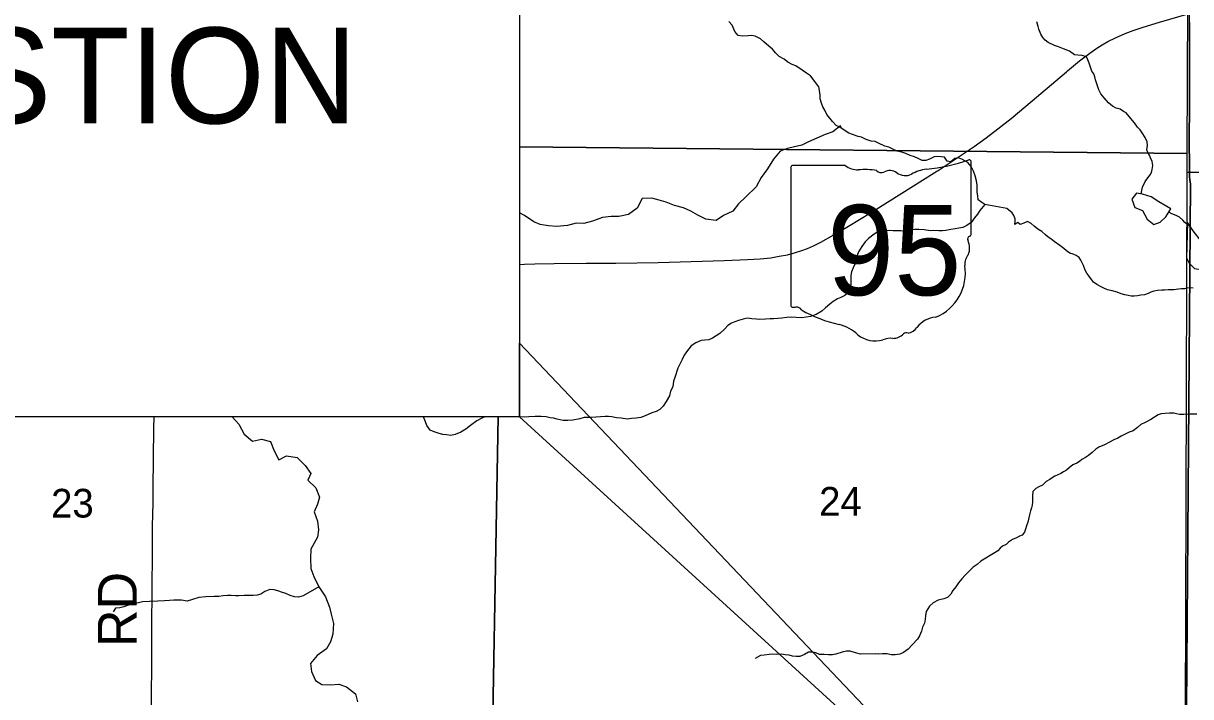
# Model space of a CAD drawing. Extents: x 0 to 34, y 0 to 22.
# Drawn here: x 3.95 to 5.655, y 18.105 to 19.089 of the extents above; entities that cross this region are included whole.
import ezdxf

# ---------------------------------------------------------------- set-up
doc = ezdxf.new("R2010")
doc.units = 0
for name, color, linetype in [('Default', 7, 'Continuous'), ('GM_X_County_Road', 7, 'Continuous'), ('GM_X_County_Road_Text', 7, 'Continuous'), ('GM_X_Minor_Lake', 7, 'Continuous'), ('GM_X_Minor_River', 7, 'Continuous'), ('GM_X_Section', 7, 'Continuous'), ('GM_X_Section_Text', 7, 'Continuous'), ('GM_X_State_Location', 7, 'Continuous'), ('GM_X_State_Route', 7, 'Continuous'), ('GM_X_State_Shield', 7, 'Continuous'), ('GM_X_Township_Road', 7, 'Continuous'), ('SH_Text', 7, 'Continuous')]:
    doc.layers.add(name, color=color, linetype=linetype)

msp = doc.modelspace()

# ---------------------------------------------------------------- linework, layer by layer
at = {"layer": 'Default'}
msp.add_lwpolyline([(4.6746, 18.6215), (5.442, 17.8135), (4.6746, 18.514)], close=True, dxfattribs=at)
at = {"layer": 'GM_X_County_Road'}
msp.add_lwpolyline([(4.1354, 17.891), (4.1352, 17.8945), (4.1354, 17.9162), (4.1358, 17.9597), (4.1364, 18.0001), (4.1364, 18.0187), (4.1366, 18.0684), (4.1368, 18.1057), (4.1371, 18.1523), (4.1375, 18.2238), (4.1376, 18.2455), (4.1378, 18.2735), (4.1381, 18.3045), (4.1385, 18.3542), (4.139, 18.3884), (4.139, 18.4101), (4.1404, 18.4971), (4.1405, 18.514)], dxfattribs=at)
at = {"layer": 'GM_X_Minor_Lake'}
for points in [[(5.6258, 18.8178), (5.6087, 18.8279), (5.5973, 18.8354), (5.5844, 18.8395), (5.5757, 18.8409), (5.5689, 18.8318), (5.5732, 18.82), (5.5846, 18.8152), (5.5915, 18.8027), (5.601, 18.7948), (5.6104, 18.7983), (5.6187, 18.806)], [(5.6187, 18.806), (5.6258, 18.8178)], [(5.649, 18.7459), (5.6533, 18.738), (5.6605, 18.7308), (5.6726, 18.729), (5.6878, 18.7329), (5.6994, 18.7413), (5.6975, 18.7546), (5.6864, 18.7595), (5.6708, 18.77), (5.6586, 18.7858), (5.6502, 18.7979)], [(5.6502, 18.7979), (5.649, 18.7459)]]:
    msp.add_lwpolyline(points, dxfattribs=at)
at = {"layer": 'GM_X_Minor_River'}
for points in [[(5.3542, 18.8243), (5.35, 18.8273), (5.3447, 18.8311), (5.3439, 18.8368), (5.3431, 18.8421), (5.3431, 18.8524), (5.3419, 18.8589), (5.3403, 18.8661), (5.3376, 18.8729), (5.3342, 18.8797), (5.3292, 18.8854), (5.3209, 18.8903), (5.3155, 18.8922), (5.3102, 18.8914), (5.3046, 18.8864), (5.2992, 18.8876), (5.2954, 18.8932), (5.2905, 18.894), (5.2855, 18.8943), (5.2802, 18.8936), (5.2734, 18.8905), (5.2681, 18.8886), (5.2628, 18.8885), (5.2567, 18.8912), (5.2514, 18.8938), (5.2453, 18.8957), (5.2388, 18.8987), (5.2328, 18.9006), (5.2263, 18.9021), (5.2206, 18.9043), (5.2141, 18.9081), (5.208, 18.9096), (5.1989, 18.9137), (5.194, 18.916), (5.1883, 18.9167), (5.1807, 18.9193), (5.1742, 18.9224), (5.1693, 18.9235), (5.1609, 18.9265), (5.1556, 18.9284), (5.1502, 18.9317), (5.1422, 18.937), (5.1369, 18.9397), (5.1319, 18.9454), (5.1277, 18.9503), (5.1235, 18.9556), (5.1205, 18.962), (5.1178, 18.967), (5.1155, 18.9723), (5.1139, 18.9787), (5.1135, 18.9841), (5.1127, 18.9905), (5.1116, 18.9962), (5.1058, 19.0038), (5.0997, 19.0121), (5.0936, 19.0159), (5.0872, 19.0204), (5.078, 19.0269), (5.0727, 19.0287), (5.0666, 19.0321), (5.0613, 19.0363), (5.0537, 19.0404), (5.0483, 19.0457), (5.0441, 19.051), (5.0388, 19.0556), (5.0315, 19.0616), (5.0266, 19.0662), (5.0186, 19.0699), (5.0136, 19.071), (5.0083, 19.0706), (5.0004, 19.0702), (4.9939, 19.071), (4.9889, 19.077), (4.9851, 19.0861), (4.9805, 19.0914)], [(5.5829, 18.8397), (5.5846, 18.8497), (5.5883, 18.8577), (5.5924, 18.8631), (5.5957, 18.8673), (5.5976, 18.8711), (5.5987, 18.8753), (5.5997, 18.8814), (5.5989, 18.8871), (5.5962, 18.8924), (5.5946, 18.8962), (5.5923, 18.9003), (5.5911, 18.9041), (5.5921, 18.9106), (5.5913, 18.9155), (5.5886, 18.9223), (5.5839, 18.9291), (5.5812, 18.9332), (5.5773, 18.9373), (5.5731, 18.9437), (5.565, 18.9528), (5.5607, 18.958), (5.5569, 18.9602), (5.5519, 18.9636), (5.5462, 18.965), (5.5408, 18.9676), (5.5347, 18.9725), (5.5285, 18.98), (5.5235, 18.9856), (5.5207, 18.9917), (5.5172, 19.0019), (5.516, 19.0064), (5.5148, 19.0106), (5.5136, 19.0151), (5.5105, 19.0189), (5.5085, 19.0246), (5.5069, 19.0306), (5.5046, 19.0355), (5.5026, 19.04), (5.4965, 19.0419), (5.49, 19.0422), (5.4854, 19.0429), (5.4778, 19.0481), (5.4694, 19.0514), (5.4617, 19.0547), (5.456, 19.0565), (5.4468, 19.061), (5.4422, 19.0643), (5.4391, 19.0681), (5.436, 19.073), (5.4332, 19.0801), (5.432, 19.0843), (5.4304, 19.0911)], [(5.1447, 18.9354), (5.1436, 18.9393), (5.1323, 18.9305), (5.1209, 18.9262), (5.0968, 18.9155), (5.0869, 18.9109), (5.0763, 18.9085), (5.0658, 18.9058), (5.0555, 18.9023), (5.0454, 18.8905), (5.0368, 18.8761), (5.0277, 18.8635), (5.0202, 18.8498), (5.0052, 18.8353), (4.9946, 18.8254), (4.9863, 18.8143), (4.9724, 18.8082), (4.9618, 18.8009), (4.9466, 18.8027), (4.9352, 18.8087), (4.9246, 18.8147), (4.914, 18.8192), (4.9011, 18.8229), (4.8886, 18.8278), (4.8787, 18.8304), (4.8677, 18.8334), (4.8537, 18.8329), (4.8462, 18.8188), (4.8337, 18.8096), (4.8194, 18.8065), (4.8084, 18.8065), (4.7959, 18.8052), (4.7812, 18.7999), (4.7683, 18.7964), (4.7573, 18.7967), (4.7448, 18.7936), (4.7289, 18.792), (4.7168, 18.793), (4.7047, 18.7952), (4.6952, 18.799), (4.6815, 18.808), (4.6746, 18.8118)], [(5.3542, 18.8243), (5.3471, 18.8152), (5.3437, 18.8102), (5.3391, 18.8045), (5.3342, 18.798), (5.3282, 18.7934), (5.3221, 18.7907), (5.3164, 18.7895), (5.3111, 18.7888), (5.3047, 18.7876), (5.2975, 18.7864), (5.2922, 18.7856), (5.2872, 18.7856), (5.28, 18.786), (5.2747, 18.7859), (5.2656, 18.787), (5.2576, 18.7878), (5.2519, 18.7877), (5.2463, 18.7866), (5.2413, 18.7858), (5.2364, 18.7854), (5.2315, 18.7857), (5.2205, 18.7857), (5.2151, 18.786), (5.2098, 18.7856), (5.2041, 18.7852), (5.1981, 18.7841), (5.1928, 18.781), (5.1845, 18.7745), (5.1795, 18.7699), (5.1747, 18.7627), (5.1698, 18.755), (5.1679, 18.7497), (5.1668, 18.744), (5.1653, 18.739), (5.1619, 18.7318), (5.1597, 18.7257), (5.1586, 18.7204), (5.1586, 18.7097), (5.1579, 18.7029), (5.1564, 18.6972), (5.1496, 18.6914), (5.1439, 18.6884), (5.139, 18.6865), (5.1329, 18.6826), (5.128, 18.6788), (5.1216, 18.6731), (5.1163, 18.6685), (5.108, 18.6635), (5.0997, 18.6608), (5.0932, 18.6596), (5.0868, 18.6588), (5.0788, 18.6592), (5.0716, 18.6595), (5.0648, 18.6591), (5.0576, 18.6583), (5.0519, 18.6575), (5.0454, 18.6571), (5.0405, 18.6571), (5.034, 18.6567), (5.0257, 18.6563), (5.0207, 18.6566), (5.0139, 18.657), (5.0071, 18.6581), (5.001, 18.6566), (4.9942, 18.655), (4.9889, 18.6527), (4.984, 18.6508), (4.979, 18.6477), (4.9741, 18.642), (4.9673, 18.6359), (4.9564, 18.629), (4.9511, 18.6263), (4.945, 18.6259), (4.9397, 18.6255), (4.9321, 18.6224), (4.9253, 18.6178), (4.9185, 18.609), (4.9151, 18.6041), (4.9121, 18.5976), (4.908, 18.59), (4.9058, 18.585), (4.9013, 18.5713), (4.8994, 18.5664), (4.8983, 18.558), (4.8949, 18.5515), (4.8934, 18.5447), (4.8886, 18.5367), (4.8844, 18.5298), (4.8795, 18.5248), (4.8742, 18.5221), (4.8678, 18.5198), (4.8579, 18.5156), (4.8519, 18.5133), (4.845, 18.5121), (4.8382, 18.5117), (4.8321, 18.5109), (4.823, 18.512), (4.8162, 18.5124), (4.8094, 18.5139), (4.8044, 18.5146)], [(5.3968, 18.8081), (5.3941, 18.8118), (5.3864, 18.8186), (5.3542, 18.8243)], [(5.6501, 18.795), (5.6465, 18.7977), (5.6434, 18.8015), (5.6388, 18.8056), (5.6338, 18.8082), (5.6273, 18.8108), (5.623, 18.813)], [(5.6587, 18.7018), (5.6545, 18.7025), (5.6496, 18.702), (5.6458, 18.7012), (5.6416, 18.7008), (5.6371, 18.7003), (5.6302, 18.6995), (5.6264, 18.6998), (5.6219, 18.6998), (5.6166, 18.6993), (5.6128, 18.6993), (5.6063, 18.6984), (5.6014, 18.6976), (5.5968, 18.696), (5.593, 18.6944), (5.5877, 18.6921), (5.5824, 18.6916), (5.5775, 18.6908), (5.5726, 18.6904), (5.568, 18.6903), (5.5638, 18.6914), (5.5588, 18.6925), (5.5535, 18.6939), (5.5474, 18.6961), (5.5401, 18.6979), (5.5336, 18.6997), (5.5279, 18.7019), (5.5241, 18.7038), (5.5179, 18.7075), (5.513, 18.7108), (5.5103, 18.7146), (5.506, 18.7202), (5.5033, 18.724), (5.5009, 18.7282), (5.4982, 18.735), (5.4966, 18.7391), (5.4947, 18.7429), (5.492, 18.7467), (5.4877, 18.7496), (5.4835, 18.7515), (5.4786, 18.7533), (5.4736, 18.7567), (5.4697, 18.7597), (5.464, 18.7645), (5.4555, 18.7701), (5.4505, 18.7742), (5.4467, 18.7764), (5.4428, 18.7798), (5.4375, 18.7847), (5.4317, 18.7884), (5.4263, 18.7925), (5.4221, 18.7966), (5.4167, 18.7996), (5.4114, 18.7969), (5.4061, 18.7949), (5.4023, 18.7979), (5.3982, 18.7948), (5.3985, 18.7993), (5.3984, 18.8031), (5.3968, 18.8081)], [(4.2548, 18.514), (4.2643, 18.5033), (4.2723, 18.4889), (4.2845, 18.4787), (4.2974, 18.4814), (4.3106, 18.4781), (4.316, 18.4645), (4.3229, 18.4513), (4.3342, 18.457), (4.3494, 18.4548), (4.3612, 18.4428), (4.3696, 18.4314), (4.3651, 18.4215), (4.3769, 18.4102), (4.3823, 18.3966), (4.3793, 18.3867), (4.3744, 18.3753), (4.3791, 18.3617), (4.3807, 18.3492), (4.3792, 18.3382), (4.3694, 18.321), (4.3691, 18.3074), (4.3696, 18.2926), (4.3738, 18.2809), (4.3815, 18.2657), (4.391, 18.251), (4.3968, 18.2362), (4.3995, 18.226), (4.4026, 18.212), (4.4016, 18.1968)], [(4.624, 18.514), (4.6192, 18.5122), (4.612, 18.508), (4.603, 18.5015), (4.5962, 18.4962), (4.5886, 18.4916), (4.5806, 18.4885), (4.5742, 18.4869), (4.5677, 18.4877), (4.5624, 18.4884), (4.5571, 18.4899), (4.5499, 18.4921), (4.5438, 18.4944), (4.5392, 18.5016), (4.5373, 18.5069), (4.5342, 18.514)], [(4.8044, 18.5146), (4.7995, 18.5146), (4.793, 18.5142), (4.7858, 18.5137), (4.7794, 18.5133), (4.7744, 18.5129), (4.7688, 18.5129), (4.7627, 18.5114), (4.7525, 18.509), (4.7452, 18.5086), (4.738, 18.5086), (4.7297, 18.5108), (4.724, 18.5123), (4.719, 18.5127), (4.7133, 18.5142), (4.7061, 18.5145), (4.6974, 18.5145), (4.6879, 18.5141), (4.6811, 18.5136), (4.6746, 18.514)], [(5.6638, 18.518), (5.6543, 18.5179), (5.6452, 18.5174), (5.6387, 18.5177), (5.6345, 18.5187), (5.6303, 18.5194), (5.6242, 18.5194), (5.6178, 18.5189), (5.6121, 18.5184), (5.6075, 18.5172), (5.6019, 18.5137), (5.597, 18.5103), (5.5886, 18.506), (5.5822, 18.5028), (5.5773, 18.4986), (5.5709, 18.4936), (5.5653, 18.4916), (5.5581, 18.4885), (5.5532, 18.4857), (5.5486, 18.483), (5.5426, 18.4807), (5.5362, 18.4772), (5.529, 18.4733), (5.521, 18.4697), (5.5165, 18.467), (5.5109, 18.462), (5.5056, 18.4574), (5.5015, 18.4547), (5.4962, 18.4516), (5.4924, 18.4488), (5.4886, 18.4465), (5.483, 18.4438), (5.4777, 18.4395), (5.4736, 18.4361), (5.4694, 18.4337), (5.4653, 18.4314), (5.4611, 18.4294), (5.4566, 18.4275), (5.4528, 18.4248), (5.449, 18.4224), (5.4441, 18.4197), (5.4385, 18.4143), (5.4332, 18.4116), (5.429, 18.4093), (5.4245, 18.405), (5.4238, 18.3985), (5.424, 18.3898), (5.4233, 18.3852), (5.4225, 18.3814), (5.4211, 18.3769), (5.4196, 18.3711), (5.4182, 18.3647), (5.4171, 18.3601), (5.4149, 18.3547), (5.4138, 18.3498), (5.412, 18.3456), (5.409, 18.3414), (5.4048, 18.3398), (5.4007, 18.3375), (5.3946, 18.3351), (5.389, 18.3312), (5.3852, 18.3278), (5.3803, 18.3254), (5.3765, 18.3223), (5.3732, 18.3185), (5.3694, 18.3158)], [(5.3694, 18.3158), (5.3482, 18.3034), (5.3429, 18.2984), (5.3373, 18.2946), (5.3256, 18.2828), (5.3206, 18.2774), (5.3157, 18.2717), (5.312, 18.266), (5.3075, 18.2606), (5.3048, 18.2553), (5.2995, 18.2503), (5.2942, 18.2484), (5.2863, 18.2465), (5.2787, 18.2426), (5.2734, 18.2377), (5.2685, 18.2297), (5.2678, 18.2236), (5.2671, 18.2186), (5.2663, 18.2125), (5.2633, 18.2068), (5.2618, 18.2011), (5.2588, 18.1943), (5.2558, 18.1893), (5.2483, 18.1809), (5.2422, 18.1748), (5.2354, 18.1698), (5.2301, 18.1675), (5.2233, 18.1663), (5.2176, 18.1667), (5.2115, 18.1678), (5.2047, 18.1678), (5.1994, 18.1674), (5.1945, 18.1677), (5.1725, 18.1676), (5.1652, 18.1695), (5.1576, 18.1717), (5.1523, 18.1717), (5.1459, 18.1705), (5.1368, 18.1675), (5.1315, 18.1667), (5.1258, 18.1666), (5.1193, 18.167), (5.1125, 18.167), (5.1076, 18.1692), (5.1026, 18.1703), (5.0965, 18.1703), (5.0909, 18.1669), (5.0841, 18.1638), (5.0787, 18.1638), (5.0734, 18.1645), (5.0685, 18.166), (5.0628, 18.1667), (5.0578, 18.1675), (5.0506, 18.1671), (5.0446, 18.1674), (5.0393, 18.167), (5.0317, 18.1662), (5.0264, 18.1654), (5.0188, 18.1612)], [(4.3815, 18.2657), (4.3584, 18.2525), (4.3515, 18.2506), (4.3455, 18.2513), (4.3394, 18.2532), (4.3329, 18.2562), (4.328, 18.2573), (4.3215, 18.2599), (4.3162, 18.2614), (4.3097, 18.2621), (4.3025, 18.2591), (4.2965, 18.2552), (4.2912, 18.2537), (4.2855, 18.2533), (4.2722, 18.2529), (4.2646, 18.2528), (4.2597, 18.2528), (4.2532, 18.2531), (4.2479, 18.2531), (4.2415, 18.2527), (4.235, 18.2519), (4.2286, 18.2515), (4.2164, 18.2511), (4.2058, 18.2503), (4.1967, 18.2472), (4.1891, 18.2449), (4.1804, 18.2463), (4.1694, 18.2463), (4.1633, 18.2459), (4.1557, 18.2455), (4.1463, 18.2447), (4.1341, 18.2446), (4.1239, 18.2438), (4.1178, 18.2426), (4.1129, 18.2415), (4.1072, 18.2403), (4.1019, 18.2384), (4.0962, 18.2365), (4.0905, 18.2349), (4.0844, 18.2345), (4.0807, 18.2292)], [(4.4016, 18.1968), (4.3982, 18.1854), (4.3926, 18.1752), (4.3786, 18.1656), (4.3692, 18.1538), (4.3708, 18.142), (4.3762, 18.1288), (4.3857, 18.1231), (4.3982, 18.1225), (4.4103, 18.1237), (4.4217, 18.1199), (4.4346, 18.1094), (4.4377, 18.0977)]]:
    msp.add_lwpolyline(points, dxfattribs=at)
at = {"layer": 'GM_X_Section'}
for points in [[(4.6746, 18.9086), (5.6498, 18.8985), (5.6542, 19.8813), (5.654, 19.9264), (4.6576, 19.9182), (4.6526, 19.2311), (4.6746, 19.2311)], [(5.6542, 19.8813), (6.7799, 19.8913), (6.7847, 18.8752), (5.6499, 18.8708), (5.6498, 18.8985)], [(4.6433, 18.514), (4.6321, 17.8882), (5.6468, 17.9172), (5.6499, 18.8708), (5.6498, 18.8985), (4.6746, 18.9086), (4.6746, 18.514)], [(5.6499, 18.8708), (6.7847, 18.8752), (6.7979, 17.8558), (5.6465, 17.841), (5.6468, 17.9172)], [(3.6261, 18.514), (3.6191, 17.892), (4.6321, 17.8882), (4.6433, 18.514)]]:
    msp.add_lwpolyline(points, close=True, dxfattribs=at)
at = {"layer": 'GM_X_State_Route'}
for points in [[(5.4752, 19.0193), (5.4928, 19.0339), (5.5076, 19.0453), (5.5177, 19.0525), (5.5256, 19.0575), (5.5338, 19.0621), (5.545, 19.0676), (5.5593, 19.0738), (5.5709, 19.0782), (5.5857, 19.0832), (5.6095, 19.0904), (5.6512, 19.1027), (5.6535, 19.1034)], [(5.6532, 19.0901), (5.6531, 19.0435), (5.6533, 19.0031), (5.6534, 18.969), (5.653, 18.9193), (5.6529, 18.9045), (5.6531, 18.8925), (5.6534, 18.8695), (5.6535, 18.8651), (5.654, 18.8601), (5.6549, 18.8539), (5.6477, 17.9606)], [(5.6477, 17.9606), (5.6549, 18.8539), (5.654, 18.8601), (5.6535, 18.8651), (5.6534, 18.8695), (5.6531, 18.8925), (5.6529, 18.9045), (5.653, 18.9193), (5.6534, 18.969), (5.6533, 19.0031), (5.6531, 19.0435), (5.6532, 19.0901)], [(5.286, 18.8738), (5.3051, 18.8863), (5.3386, 18.9088), (5.3562, 18.9215), (5.3735, 18.9346), (5.3929, 18.95), (5.4144, 18.9679), (5.4737, 19.018), (5.4752, 19.0193)], [(4.6746, 18.7366), (4.6815, 18.7369), (4.697, 18.7373), (4.725, 18.738), (4.7716, 18.7384), (4.8151, 18.7386), (4.8772, 18.7395), (4.9734, 18.7423), (5.0076, 18.7437), (5.0261, 18.7449), (5.0415, 18.7465), (5.0537, 18.7485), (5.0659, 18.7509), (5.0778, 18.754), (5.0867, 18.7568), (5.0953, 18.7601), (5.1038, 18.7638), (5.1148, 18.7694), (5.1337, 18.7801), (5.1552, 18.7926), (5.1871, 18.8118), (5.2161, 18.8298), (5.2634, 18.8595), (5.2843, 18.8728), (5.286, 18.8738)]]:
    msp.add_lwpolyline(points, dxfattribs=at)
at = {"layer": 'GM_X_State_Shield'}
for p, q in [((5.1504, 18.8811), (5.0732, 18.8811)), ((5.3343, 18.7814), (5.3343, 18.8861)), ((5.0706, 18.8777), (5.0706, 18.6776)), ((5.3343, 18.7814), (5.3343, 18.7814))]:
    msp.add_line(p, q, dxfattribs=at)
for centre, radius, start, end in [((5.0736, 18.8781), 0.00305, 98.1301, 188.1301), ((5.1688, 18.9044), 0.0296, 231.6195, 271.1119), ((5.2404, 19.154), 0.2796, 275.8445, 288.9065), ((5.3314, 18.8865), 0.00294, 351.8621, 97.738), ((5.1787, 18.7688), 0.1064, 80.4867, 94.9883), ((5.2028, 18.8792), 0.00855, 219.7921, 297.1024), ((5.2153, 18.856), 0.0178, 54.4667, 119.1411), ((5.2383, 18.8878), 0.0214, 233.8562, 294.8282), ((5.276, 18.82), 0.0563, 97.3462, 120.7689), ((5.3336, 18.7737), 0.00454, 107.944, 210.337), ((5.3312, 18.781), 0.00314, 289.6038, 7.7341), ((5.3047, 18.7605), 0.0273, 340.033, 23.6496), ((5.3448, 18.7376), 0.0198, 136.8065, 186.9296), ((5.256, 18.7243), 0.0699, 292.3089, 8.9858), ((5.0737, 18.6771), 0.00308, 171.9584, 258.3066), ((5.0741, 18.6976), 0.0235, 267.339, 280.6039), ((5.079, 18.666), 0.00848, 29.7484, 93.2717), ((5.186, 18.8458), 0.2019, 240.4129, 257.1985), ((5.2855, 18.6214), 0.0383, 94.4031, 142.5768), ((5.1258, 18.5877), 0.0632, 47.1842, 75.836), ((5.237, 18.6582), 0.0226, 282.8732, 323.2771), ((5.1941, 18.665), 0.0401, 230.7004, 286.2918), ((5.2173, 18.5959), 0.0329, 85.6951, 111.2099), ((5.2202, 18.6501), 0.0214, 268.777, 315.5493), ((5.2396, 18.6307), 0.00601, 65.7517, 132.6484)]:
    msp.add_arc(centre, radius, start, end, dxfattribs=at)
at = {"layer": 'GM_X_Township_Road'}
msp.add_lwpolyline([(5.6551, 18.8533), (5.6542, 18.8596), (5.6537, 18.8646), (5.6536, 18.869), (5.6533, 18.8919), (5.6531, 18.904), (5.6532, 18.9188), (5.6536, 18.9685), (5.6535, 19.0026), (5.6533, 19.0429), (5.6534, 19.0895), (5.6535, 19.1034)], dxfattribs=at)
at = {"layer": 'SH_Text'}
msp.add_lwpolyline([(2.4548, 19.2311), (4.6746, 19.2311), (4.6746, 18.514), (2.4548, 18.514)], close=True, dxfattribs=at)

# ---------------------------------------------------------------- texts
at = {"layer": 'GM_X_County_Road_Text'}
msp.add_text('RD', height=0.05682, rotation=90, dxfattribs=at).set_placement((4.1153, 18.1778))
at = {"layer": 'GM_X_Section_Text'}
for s, p in [('23', (3.9901, 18.367)), ('24', (5.1122, 18.3698))]:
    msp.add_text(s, height=0.04186, rotation=0, dxfattribs=at).set_placement(p)
at = {"layer": 'GM_X_State_Location'}
for s in ['s', 'r']:
    msp.add_text(s, height=0.000189, dxfattribs=at).set_placement((5.1995, 18.7643))
msp.add_text('95', height=0.000189, rotation=0, dxfattribs=at).set_placement((5.1518, 18.7506))
at = {"layer": 'GM_X_State_Shield'}
msp.add_text('95', height=0.13184, dxfattribs=at).set_placement((5.1239, 18.6917))
at = {"layer": 'SH_Text'}
msp.add_text('BEGIN ACQUISTION', height=0.14, dxfattribs=at).set_placement((2.6379, 18.9426))

doc.saveas('drawing.dxf')
